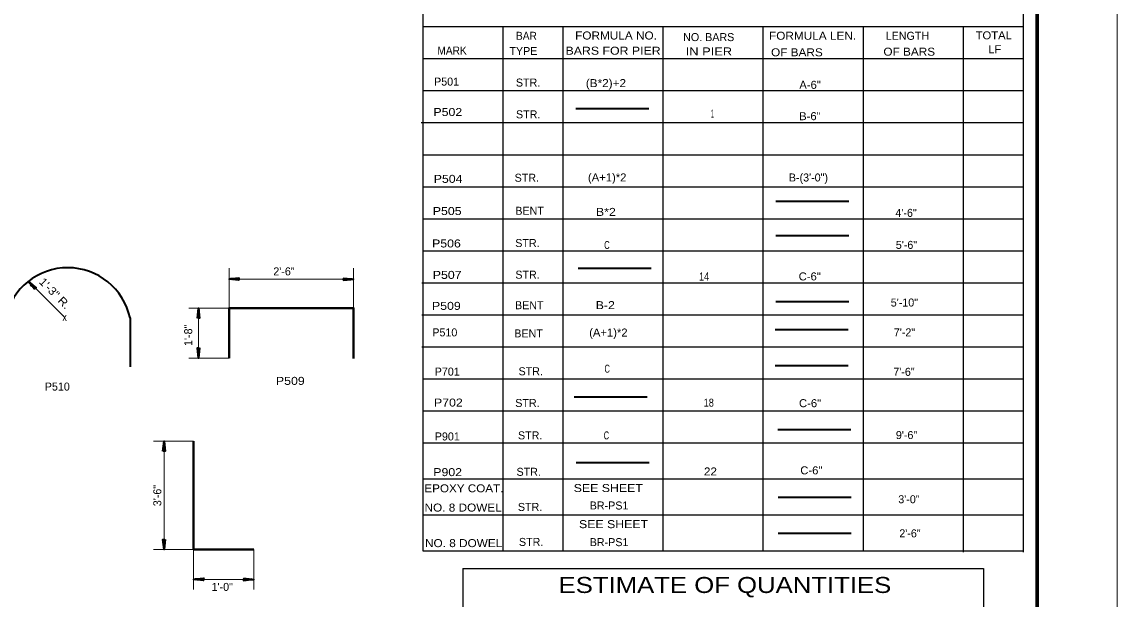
# Model space of a CAD drawing. Extents: x 14.14 to 17.34, y -1.61 to 0.38.
# Drawn here: x 16.199 to 17.339, y -1.033 to -0.432 of the extents above; entities that cross this region are included whole.
import ezdxf
from ezdxf.enums import TextEntityAlignment as Align

# ---------------------------------------------------------------- set-up
doc = ezdxf.new("R2010")
doc.units = 0
doc.header["$LTSCALE"] = 0.0033
doc.header["$PDMODE"] = 32
doc.header["$PDSIZE"] = 0.00165
doc.layers.add('1', color=7, linetype='Continuous', lineweight=40)

msp = doc.modelspace()

# ---------------------------------------------------------------- linework, layer by layer
at = {"layer": '1', "lineweight": 13}
for p, q in [((17.33925, 0.381833), (17.33925, -1.604583)), ((16.414917, -0.729667), (16.414917, -0.688)), ((16.544583, -0.729667), (16.544583, -0.688)), ((16.24375, -0.739), (16.206667, -0.701917)), ((16.415417, -0.699583), (16.543, -0.699583)), ((16.414917, -0.729667), (16.37325, -0.729667)), ((16.383167, -0.729667), (16.383167, -0.781167)), ((16.414917, -0.781917), (16.37325, -0.781917)), ((16.378083, -0.868167), (16.336417, -0.868167)), ((16.34725, -0.868167), (16.34725, -0.979917)), ((16.378083, -0.981167), (16.336417, -0.981167)), ((16.378083, -0.981167), (16.378083, -1.022833)), ((16.440583, -0.981167), (16.440583, -1.022833)), ((16.378083, -1.012167), (16.440583, -1.012167))]:
    msp.add_line(p, q, dxfattribs=at)
at = {"layer": '1', "lineweight": 25}
for p, q in [((16.6165, -0.403167), (16.6165, -0.982417)), ((17.2415, -0.403167), (17.2415, -0.983833)), ((16.6165, -0.436667), (17.2415, -0.436667)), ((16.699833, -0.436667), (16.699833, -0.98325)), ((16.762333, -0.436667), (16.762333, -0.982667)), ((16.8665, -0.436667), (16.8665, -0.982667)), ((16.970667, -0.436667), (16.970667, -0.982667)), ((17.074833, -0.436667), (17.074833, -0.98325)), ((17.179, -0.436667), (17.179, -0.983833)), ((16.6165, -0.47), (17.2415, -0.47)), ((16.6165, -0.503333), (17.2415, -0.503333)), ((16.615, -0.536667), (17.2415, -0.536667)), ((16.6165, -0.57), (17.2415, -0.57)), ((16.6165, -0.603333), (17.2415, -0.603333)), ((16.6165, -0.636667), (17.2415, -0.636667)), ((16.6165, -0.67), (17.2415, -0.67)), ((16.61575, -0.703333), (17.2415, -0.703333)), ((16.61575, -0.736667), (17.2415, -0.736667)), ((16.61575, -0.77), (17.2415, -0.77)), ((16.617333, -0.803333), (17.2415, -0.803333)), ((16.6165, -0.836667), (17.2415, -0.836667)), ((16.6165, -0.87), (17.2415, -0.87)), ((16.6165, -0.9075), (17.2415, -0.9075)), ((16.6165, -0.945), (17.2415, -0.945)), ((16.6165, -0.9825), (17.2415, -0.9825)), ((16.658417, -1.001), (16.658417, -1.167833)), ((16.658417, -1.001), (17.200083, -1.001)), ((17.200083, -1.001), (17.200083, -1.167833))]:
    msp.add_line(p, q, dxfattribs=at)
at = {"layer": '1', "lineweight": 35}
for p, q in [((16.775833, -0.521833), (16.851833, -0.521833)), ((16.984167, -0.61825), (17.060167, -0.61825)), ((16.984167, -0.65425), (17.060167, -0.65425)), ((16.778167, -0.688083), (16.854167, -0.688083)), ((16.213417, -0.7095), (16.205917, -0.702)), ((16.212667, -0.709917), (16.207667, -0.703667)), ((16.2125, -0.709917), (16.207667, -0.70375)), ((16.2125, -0.709917), (16.207667, -0.70375)), ((16.212583, -0.709833), (16.207667, -0.70375)), ((16.212667, -0.709917), (16.207917, -0.703583)), ((16.213833, -0.708667), (16.208083, -0.704)), ((16.21375, -0.708833), (16.208083, -0.704167)), ((16.213917, -0.708583), (16.208167, -0.704)), ((16.214, -0.708417), (16.20825, -0.703833)), ((16.212917, -0.708917), (16.2095, -0.705667)), ((16.4255, -0.699583), (16.414917, -0.699583)), ((16.42525, -0.700417), (16.417417, -0.699417)), ((16.42525, -0.700417), (16.417417, -0.699583)), ((16.42525, -0.700583), (16.417417, -0.699667)), ((16.42525, -0.700583), (16.417417, -0.699667)), ((16.42525, -0.7005), (16.417417, -0.699667)), ((16.42525, -0.6985), (16.417917, -0.699333)), ((16.42525, -0.698667), (16.417917, -0.699417)), ((16.42525, -0.69875), (16.417917, -0.699583)), ((16.425333, -0.698917), (16.418, -0.699667)), ((16.534, -0.699583), (16.544583, -0.699583)), ((16.534167, -0.70025), (16.5415, -0.6995)), ((16.53425, -0.698583), (16.542083, -0.6995)), ((16.53425, -0.698583), (16.542083, -0.6995)), ((16.53425, -0.698667), (16.542083, -0.6995)), ((16.53425, -0.69875), (16.542083, -0.699583)), ((16.53425, -0.69875), (16.542083, -0.69975)), ((16.53425, -0.700417), (16.541583, -0.699583)), ((16.53425, -0.7005), (16.541583, -0.69975)), ((16.53425, -0.700667), (16.541583, -0.699833)), ((16.984167, -0.722833), (17.060167, -0.722833)), ((16.311917, -0.739917), (16.311917, -0.79075)), ((16.382167, -0.74), (16.383083, -0.732167)), ((16.382167, -0.74), (16.383083, -0.732167)), ((16.38225, -0.74), (16.383083, -0.732167)), ((16.382333, -0.74), (16.383167, -0.732167)), ((16.382333, -0.74), (16.383333, -0.732167)), ((16.383833, -0.740083), (16.383083, -0.73275)), ((16.383167, -0.74025), (16.383167, -0.729667)), ((16.384, -0.74), (16.383167, -0.732667)), ((16.384083, -0.74), (16.383333, -0.732667)), ((16.38425, -0.74), (16.383417, -0.732667)), ((16.983417, -0.752167), (17.059417, -0.752167)), ((16.382083, -0.7715), (16.382917, -0.778833)), ((16.38225, -0.7715), (16.383, -0.778833)), ((16.382333, -0.7715), (16.383167, -0.778833)), ((16.3825, -0.771417), (16.38325, -0.77875)), ((16.384, -0.7715), (16.383, -0.779333)), ((16.383167, -0.77125), (16.383167, -0.781833)), ((16.384, -0.7715), (16.383167, -0.779333)), ((16.384167, -0.7715), (16.38325, -0.779333)), ((16.384167, -0.7715), (16.38325, -0.779333)), ((16.384083, -0.7715), (16.38325, -0.779333)), ((16.983417, -0.789583), (17.059417, -0.789583)), ((16.774083, -0.822167), (16.850083, -0.822167)), ((16.986167, -0.856), (17.062167, -0.856)), ((16.34625, -0.8785), (16.347167, -0.870667)), ((16.34625, -0.8785), (16.347167, -0.870667)), ((16.346333, -0.8785), (16.347167, -0.870667)), ((16.346417, -0.8785), (16.34725, -0.870667)), ((16.346417, -0.8785), (16.347417, -0.870667)), ((16.347917, -0.878583), (16.347167, -0.87125)), ((16.34725, -0.87875), (16.34725, -0.868167)), ((16.348083, -0.8785), (16.34725, -0.871167)), ((16.348167, -0.8785), (16.347417, -0.871167)), ((16.348333, -0.8785), (16.3475, -0.871167)), ((16.776167, -0.890583), (16.852167, -0.890583)), ((16.986583, -0.926583), (17.062583, -0.926583)), ((16.986583, -0.964167), (17.062583, -0.964167)), ((16.346167, -0.970833), (16.347, -0.978167)), ((16.346333, -0.970833), (16.347083, -0.978167)), ((16.346417, -0.970833), (16.34725, -0.978167)), ((16.346583, -0.97075), (16.347333, -0.978083)), ((16.348083, -0.970833), (16.347083, -0.978667)), ((16.34725, -0.970583), (16.34725, -0.981167)), ((16.348083, -0.970833), (16.34725, -0.978667)), ((16.34825, -0.970833), (16.347333, -0.978667)), ((16.34825, -0.970833), (16.347333, -0.978667)), ((16.348167, -0.970833), (16.347333, -0.978667)), ((16.388667, -1.012167), (16.378083, -1.012167)), ((16.388417, -1.013), (16.380583, -1.012)), ((16.388417, -1.013), (16.380583, -1.012167)), ((16.388417, -1.013167), (16.380583, -1.01225)), ((16.388417, -1.013167), (16.380583, -1.01225)), ((16.388417, -1.013083), (16.380583, -1.01225)), ((16.388417, -1.011083), (16.381083, -1.011917)), ((16.388417, -1.01125), (16.381083, -1.012)), ((16.388417, -1.011333), (16.381083, -1.012167)), ((16.3885, -1.0115), (16.381167, -1.01225)), ((16.43, -1.012167), (16.440583, -1.012167)), ((16.430167, -1.012833), (16.4375, -1.012083)), ((16.43025, -1.011167), (16.438083, -1.012083)), ((16.43025, -1.011167), (16.438083, -1.012083)), ((16.43025, -1.01125), (16.438083, -1.012083)), ((16.43025, -1.011333), (16.438083, -1.012167)), ((16.43025, -1.011333), (16.438083, -1.012333)), ((16.43025, -1.013), (16.437583, -1.012167)), ((16.43025, -1.013083), (16.437583, -1.012333)), ((16.43025, -1.01325), (16.437583, -1.012417))]:
    msp.add_line(p, q, dxfattribs=at)
at = {"layer": '1', "lineweight": 70}
msp.add_lwpolyline([(17.256, -1.521417), (17.256, 0.298667), (14.309333, 0.298667), (14.309333, -1.521417)], dxfattribs=at)
at = {"layer": '1', "lineweight": 35}
for points in [[(16.21275, -0.710167), (16.205917, -0.702), (16.21425, -0.708667), (16.213, -0.709083)], [(16.4255, -0.700667), (16.414917, -0.699583), (16.4255, -0.698417), (16.424917, -0.699583)], [(16.42475, -0.699667), (16.420083, -0.69975), (16.420083, -0.699667), (16.421, -0.699667), (16.42475, -0.69975), (16.42175, -0.699833), (16.424917, -0.699917), (16.422667, -0.7), (16.424917, -0.700083), (16.421417, -0.699833), (16.41675, -0.699667), (16.417667, -0.699417), (16.416417, -0.699417), (16.42475, -0.699417), (16.422333, -0.69925), (16.424917, -0.69925), (16.419583, -0.699667), (16.424917, -0.699)], [(16.534, -0.6985), (16.544583, -0.699583), (16.534, -0.70075), (16.534583, -0.699583)], [(16.53475, -0.6995), (16.539417, -0.699417), (16.539417, -0.6995), (16.5385, -0.6995), (16.53475, -0.699417), (16.53775, -0.699333), (16.534583, -0.69925), (16.536833, -0.699167), (16.534583, -0.699083), (16.538083, -0.699333), (16.54275, -0.6995), (16.541833, -0.69975), (16.543083, -0.69975), (16.53475, -0.69975), (16.537167, -0.699917), (16.534583, -0.699917), (16.539917, -0.6995), (16.534583, -0.700167)], [(16.382083, -0.74025), (16.383167, -0.729667), (16.384333, -0.74025), (16.383167, -0.739667)], [(16.383083, -0.7395), (16.383, -0.734833), (16.383083, -0.734833), (16.383083, -0.73575), (16.383, -0.7395), (16.382917, -0.7365), (16.382833, -0.739667), (16.38275, -0.737417), (16.382667, -0.739667), (16.382917, -0.736167), (16.383083, -0.7315), (16.383333, -0.732417), (16.383333, -0.731167), (16.383333, -0.7395), (16.3835, -0.737083), (16.3835, -0.739667), (16.383083, -0.734333), (16.38375, -0.739667)], [(16.38425, -0.77125), (16.383167, -0.781833), (16.382, -0.77125), (16.383167, -0.771833)], [(16.38325, -0.772), (16.383333, -0.776667), (16.38325, -0.776667), (16.38325, -0.77575), (16.383333, -0.772), (16.383417, -0.775), (16.3835, -0.771833), (16.383583, -0.774083), (16.383667, -0.771833), (16.383417, -0.775333), (16.38325, -0.78), (16.383, -0.779083), (16.383, -0.780333), (16.383, -0.772), (16.382833, -0.774417), (16.382833, -0.771833), (16.38325, -0.777167), (16.382583, -0.771833)], [(16.346167, -0.87875), (16.34725, -0.868167), (16.348417, -0.87875), (16.34725, -0.878167)], [(16.347167, -0.878), (16.347083, -0.873333), (16.347167, -0.873333), (16.347167, -0.87425), (16.347083, -0.878), (16.347, -0.875), (16.346917, -0.878167), (16.346833, -0.875917), (16.34675, -0.878167), (16.347, -0.874667), (16.347167, -0.87), (16.347417, -0.870917), (16.347417, -0.869667), (16.347417, -0.878), (16.347583, -0.875583), (16.347583, -0.878167), (16.347167, -0.872833), (16.347833, -0.878167)], [(16.348333, -0.970583), (16.34725, -0.981167), (16.346083, -0.970583), (16.34725, -0.971167)], [(16.347333, -0.971333), (16.347417, -0.976), (16.347333, -0.976), (16.347333, -0.975083), (16.347417, -0.971333), (16.3475, -0.974333), (16.347583, -0.971167), (16.347667, -0.973417), (16.34775, -0.971167), (16.3475, -0.974667), (16.347333, -0.979333), (16.347083, -0.978417), (16.347083, -0.979667), (16.347083, -0.971333), (16.346917, -0.97375), (16.346917, -0.971167), (16.347333, -0.9765), (16.346667, -0.971167)], [(16.388667, -1.01325), (16.378083, -1.012167), (16.388667, -1.011), (16.388083, -1.012167)], [(16.387917, -1.01225), (16.38325, -1.012333), (16.38325, -1.01225), (16.384167, -1.01225), (16.387917, -1.012333), (16.384917, -1.012417), (16.388083, -1.0125), (16.385833, -1.012583), (16.388083, -1.012667), (16.384583, -1.012417), (16.379917, -1.01225), (16.380833, -1.012), (16.379583, -1.012), (16.387917, -1.012), (16.3855, -1.011833), (16.388083, -1.011833), (16.38275, -1.01225), (16.388083, -1.011583)], [(16.43, -1.011083), (16.440583, -1.012167), (16.43, -1.013333), (16.430583, -1.012167)], [(16.43075, -1.012083), (16.435417, -1.012), (16.435417, -1.012083), (16.4345, -1.012083), (16.43075, -1.012), (16.43375, -1.011917), (16.430583, -1.011833), (16.432833, -1.01175), (16.430583, -1.011667), (16.434083, -1.011917), (16.43875, -1.012083), (16.437833, -1.012333), (16.439083, -1.012333), (16.43075, -1.012333), (16.433167, -1.0125), (16.430583, -1.0125), (16.435917, -1.012083), (16.430583, -1.01275)]]:
    msp.add_lwpolyline(points, close=True, dxfattribs=at)
for points in [[(16.2095, -0.705667), (16.21025, -0.70625), (16.21275, -0.709), (16.210583, -0.707), (16.21275, -0.70925), (16.211083, -0.707667), (16.21275, -0.709333), (16.210333, -0.706667), (16.20725, -0.70325), (16.208, -0.703833), (16.207083, -0.702833), (16.213, -0.708833), (16.2115, -0.706917), (16.213333, -0.70875), (16.20925, -0.70525), (16.213417, -0.708667), (16.212917, -0.708917), (16.212583, -0.709833), (16.212583, -0.7095), (16.21275, -0.709083), (16.2125, -0.708917), (16.212333, -0.70925), (16.213, -0.708833), (16.2135, -0.708667), (16.213917, -0.7085)], [(16.42475, -0.699667), (16.425167, -0.700417), (16.424917, -0.700167), (16.42475, -0.699833), (16.4245, -0.699917), (16.424667, -0.70025), (16.424833, -0.6995), (16.425, -0.699), (16.42525, -0.698583)], [(16.53475, -0.6995), (16.534333, -0.69875), (16.534583, -0.699), (16.53475, -0.699333), (16.535, -0.69925), (16.534833, -0.698917), (16.534667, -0.699667), (16.5345, -0.700167), (16.53425, -0.700583)], [(16.383083, -0.7395), (16.382333, -0.739917), (16.382583, -0.739667), (16.382917, -0.7395), (16.382833, -0.73925), (16.3825, -0.739417), (16.38325, -0.739583), (16.38375, -0.73975), (16.384167, -0.74)], [(16.38325, -0.772), (16.384, -0.771583), (16.38375, -0.771833), (16.383417, -0.772), (16.3835, -0.77225), (16.383833, -0.772083), (16.383083, -0.771917), (16.382583, -0.77175), (16.382167, -0.7715)], [(16.347167, -0.878), (16.346417, -0.878417), (16.346667, -0.878167), (16.347, -0.878), (16.346917, -0.87775), (16.346583, -0.877917), (16.347333, -0.878083), (16.347833, -0.87825), (16.34825, -0.8785)], [(16.347333, -0.971333), (16.348083, -0.970917), (16.347833, -0.971167), (16.3475, -0.971333), (16.347583, -0.971583), (16.347917, -0.971417), (16.347167, -0.97125), (16.346667, -0.971083), (16.34625, -0.970833)], [(16.387917, -1.01225), (16.388333, -1.013), (16.388083, -1.01275), (16.387917, -1.012417), (16.387667, -1.0125), (16.387833, -1.012833), (16.388, -1.012083), (16.388167, -1.011583), (16.388417, -1.011167)], [(16.43075, -1.012083), (16.430333, -1.011333), (16.430583, -1.011583), (16.43075, -1.011917), (16.431, -1.011833), (16.430833, -1.0115), (16.430667, -1.01225), (16.4305, -1.01275), (16.43025, -1.013167)]]:
    msp.add_lwpolyline(points, dxfattribs=at)
at = {"layer": '1'}
for points in [[(16.414917, -0.781917), (16.414917, -0.729667), (16.544583, -0.729667), (16.544583, -0.78225)], [(16.378083, -0.868167), (16.378083, -0.981167), (16.440583, -0.981167)]]:
    msp.add_lwpolyline(points, dxfattribs=at)
at = {"layer": '1', "lineweight": 35}
msp.add_arc((16.247046, -0.754096), 0.066402, 12.33016, 167.37526, dxfattribs=at)
at = {"layer": '1'}
msp.add_point((16.2095, -0.705667), dxfattribs=at)

# ---------------------------------------------------------------- texts
for s, height, width, p in [('BAR', 0.008334, 0.95, (16.713583, -0.450417)), ('FORMULA NO.', 0.008334, 1.1, (16.775167, -0.450083)), ('FORMULA LEN.', 0.008334, 1.1, (16.977, -0.450333)), ('TOTAL', 0.008334, 1.05, (17.192, -0.449917)), ('MARK', 0.008334, 0.95, (16.63175, -0.46575)), ('BARS FOR PIER', 0.008334, 1.15, (16.765167, -0.465917)), ('IN PIER', 0.008334, 1.2, (16.89025, -0.466667)), ('OF BARS', 0.008334, 1.1, (16.979083, -0.467583)), ('OF BARS', 0.008334, 1.1, (17.096, -0.466917)), ('LF', 0.008334, 1.05, (17.205167, -0.464333)), ('(B*2)+2', 0.008334, 1.1, (16.78625, -0.499667)), ('A-6"', 0.008334, 1.05, (17.0085, -0.501417)), ('P502', 0.008334, 1.15, (16.627667, -0.52975)), ('B-6"', 0.008334, 1.05, (17.008333, -0.534083)), ('P504', 0.008334, 1.15, (16.628, -0.599333)), ('(A+1)*2', 0.008334, 1.05, (16.7885, -0.597833)), ('P505', 0.008334, 1.15, (16.627, -0.632833)), ('B*2', 0.008334, 1.15, (16.796833, -0.63375)), ('P506', 0.008334, 1.15, (16.62625, -0.666583)), ('C', 0.008334, 0.65, (16.805417, -0.66825)), ('P507', 0.008334, 1.15, (16.627, -0.699333)), ('14', 0.008334, 0.85, (16.904083, -0.701)), ('C-6"', 0.008334, 1.05, (17.007833, -0.700917)), ('P509', 0.008334, 1.15, (16.626167, -0.731583)), ('B-2', 0.008334, 1.15, (16.796583, -0.730833)), ('(A+1)*2', 0.008334, 1.05, (16.78975, -0.759333)), ('C', 0.008334, 0.65, (16.805667, -0.797)), ('P509', 0.008334, 1.15, (16.46375, -0.809667)), ('P702', 0.008334, 1.15, (16.62825, -0.83225)), ('18', 0.008334, 0.85, (16.909, -0.832333)), ('C-6"', 0.008334, 1.05, (17.008167, -0.832917)), ('C', 0.008334, 0.65, (16.804833, -0.866417)), ('P902', 0.008334, 1.15, (16.6275, -0.904667)), ('22', 0.008334, 1.1, (16.909167, -0.904)), ('C-6"', 0.008334, 1.05, (17.0095, -0.902833)), ('EPOXY COAT.', 0.00825, 1.1, (16.61825, -0.9215)), ('SEE SHEET', 0.008334, 1.15, (16.773667, -0.92125)), ('NO. 8 DOWEL', 0.008334, 1.1, (16.618417, -0.941583)), ('SEE SHEET', 0.008334, 1.15, (16.779167, -0.958833)), ('NO. 8 DOWEL', 0.008334, 1.1, (16.618917, -0.978583)), ('ESTIMATE OF QUANTITIES', 0.01667, 1.2, (16.757917, -1.026333))]:
    msp.add_text(s, height=height, dxfattribs=dict(at, width=width)).set_placement(p)
for s, p in [('NO. BARS', (16.887583, -0.45175)), ('LENGTH', (17.098417, -0.450417)), ('TYPE', (16.70675, -0.46625)), ('P501', (16.628333, -0.498083)), ('STR.', (16.7135, -0.499083)), ('STR.', (16.713583, -0.532167)), ('STR.', (16.712167, -0.598167)), ('B-(3\'-0")', (16.997583, -0.597917)), ('BENT', (16.712917, -0.632583)), ('4\'-6"', (17.1085, -0.63475)), ('STR.', (16.712833, -0.666167)), ('5\'-6"', (17.108917, -0.668083)), ('2\'-6"', (16.461, -0.695667)), ('STR.', (16.712917, -0.699083)), ('BENT', (16.712583, -0.730917)), ('5\'-10"', (17.103667, -0.728083)), ('P510', (16.6265, -0.759167)), ('BENT', (16.711833, -0.76025)), ('7\'-2"', (17.106833, -0.759167)), ('P701', (16.629, -0.8)), ('STR.', (16.71625, -0.799667)), ('7\'-6"', (17.106333, -0.80025)), ('P510', (16.223167, -0.815583)), ('STR.', (16.712833, -0.832667)), ('P901', (16.629083, -0.8675)), ('STR.', (16.715667, -0.866417)), ('9\'-6"', (17.109, -0.866083)), ('STR.', (16.714167, -0.904333)), ('STR.', (16.715583, -0.940917)), ('BR-PS1', (16.790333, -0.939417)), ('3\'-0"', (17.1115, -0.932917)), ('STR.', (16.716667, -0.977333)), ('BR-PS1', (16.790333, -0.977583)), ('1\'-0"', (16.39675, -1.024167))]:
    msp.add_text(s, height=0.008334, dxfattribs=at).set_placement(p)
for s, width, p in [('1', 0.4, (16.917958, -0.5315)), ('x', 0.85, (16.243792, -0.743167))]:
    msp.add_text(s, height=0.008334, dxfattribs=dict(at, width=width)).set_placement(p, align=Align.CENTER)
at = {"layer": '1', "width": 1.1}
msp.add_text('1\'-3" R.', height=0.008333, rotation=315, dxfattribs=at).set_placement((16.216417, -0.703083))
at = {"layer": '1'}
for s, p in [('1\'-8"', (16.376583, -0.769167)), ('3\'-6"', (16.344417, -0.936))]:
    msp.add_text(s, height=0.008334, rotation=90, dxfattribs=at).set_placement(p)
msp.add_text('2\'-6"', height=0.008334, dxfattribs=at).set_placement((17.123667, -0.968417), align=Align.CENTER)

doc.saveas('drawing.dxf')
